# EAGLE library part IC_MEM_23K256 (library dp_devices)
256K SPI Bus Low power Serial SRAM
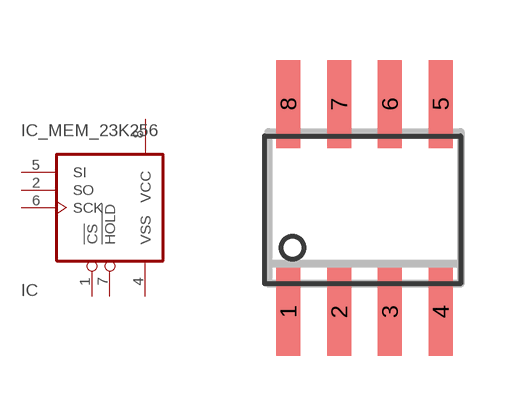
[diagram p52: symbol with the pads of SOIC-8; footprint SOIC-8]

Designator prefix IC

## IC_MEM_23K256  [SOIC-8]
1  !CS  in
2  SO  out
4  VSS  pwr
5  SI  in
6  SCK  in
7  !HOLD  in
8  VCC  pwr

## Footprint SOIC-8 (pad centres in mm)
smd 0.6 x 2.2: 1 -1.905,-2.6; 2 -0.635,-2.6; 3 0.635,-2.6; 4 1.905,-2.6; 5 1.905,2.6; 6 0.635,2.6; 7 -0.635,2.6; 8 -1.905,2.6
